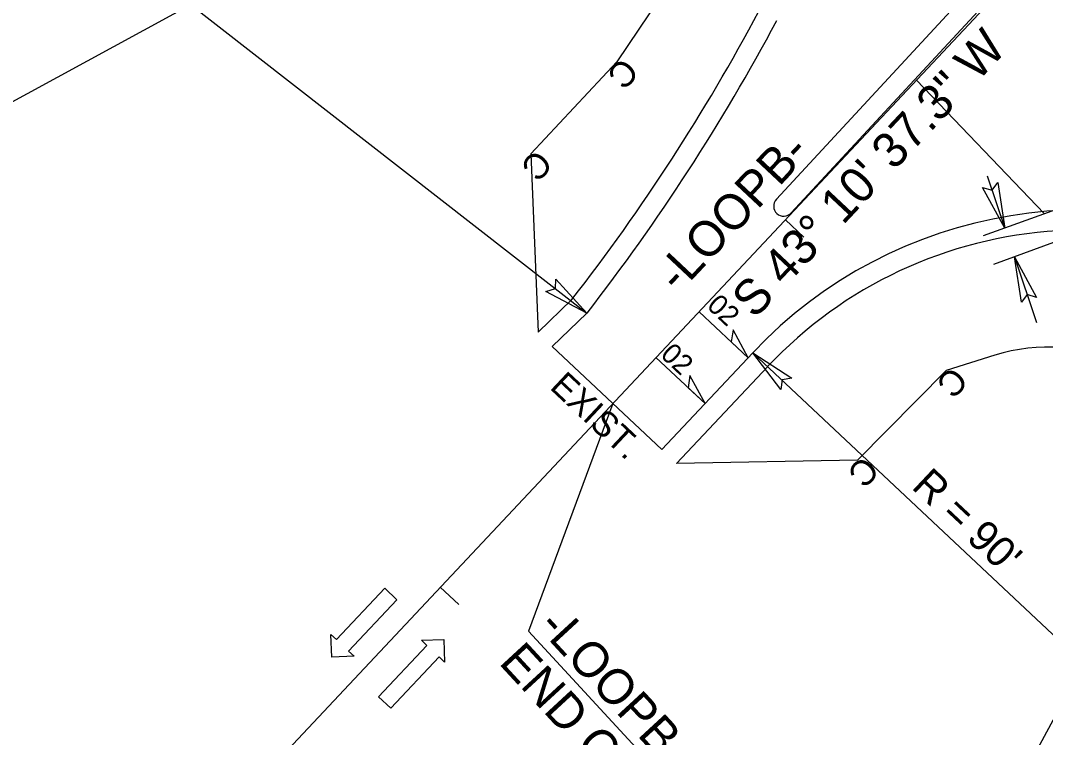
# Model space of a CAD drawing. Extents: x 1702862 to 1704514, y 793768 to 796215.
# Drawn here: x 1703113.3 to 1703316.6, y 795050.3 to 795192.6 of the extents above; entities that cross this region are included whole.
import ezdxf

# ---------------------------------------------------------------- set-up
doc = ezdxf.new("R2010")
doc.units = 0
for name, color, linetype in [('Prop Conc 5in Monolithic Surface Mount Island', 7, 'Continuous'), ('Prop Dimension', 7, 'Continuous'), ('Prop Dimension Text', 7, 'Continuous'), ('Prop DSN Text', 7, 'Continuous'), ('Prop EOT', 7, 'Continuous'), ('Prop Horizontal Alignment', 7, 'Continuous'), ('Prop Horizontal Alignment Direction Label', 7, 'Continuous'), ('Prop Horizontal Alignment Tick Small', 7, 'Continuous'), ('Prop Lane Arrow CELL', 7, 'Continuous'), ('Prop Leader Line Medium', 7, 'Continuous'), ('Prop Paved Shoulder', 7, 'Continuous'), ('Prop SS Cut Line', 7, 'Continuous'), ('Prop SS Misc', 7, 'Continuous'), ('Prop SS Transition Line', 7, 'Continuous'), ('Prop Superelevation  Arrow CELL', 7, 'Continuous'), ('Prop Superelevation Label', 7, 'Continuous'), ('Prop Terminator CELL', 7, 'Continuous')]:
    doc.layers.add(name, color=color, linetype=linetype)

msp = doc.modelspace()

# ---------------------------------------------------------------- linework, layer by layer
at = {"layer": 'Prop Conc 5in Monolithic Surface Mount Island'}
for p, q in [((1703304.39, 795201.63), (1703263.21, 795157.11)), ((1703304.39, 795201.63), (1703263.21, 795157.11)), ((1703266.15, 795154.39), (1703307.33, 795198.91)), ((1703266.15, 795154.39), (1703307.33, 795198.91))]:
    msp.add_line(p, q, dxfattribs=at)
for start, end in [(137.2317, 227.2317), (137.2317, 227.2317), (227.2317, 317.2317), (227.2317, 317.2317)]:
    msp.add_arc((1703264.68, 795155.75), 2, start, end, dxfattribs=at)
at = {"layer": 'Prop Dimension'}
for p, q in [((1702910.07, 795380.31), (1703225.66, 795134.54)), ((1702911.8, 795067.36), (1703262.92, 795258.97)), ((1703305.02, 795161.75), (1703308.5, 795151.4)), ((1703317.84, 795154.78), (1703304.2, 795149.85)), ((1703320.17, 795149.24), (1703306.25, 795144.2)), ((1703310.41, 795145.71), (1703314.8, 795132.63)), ((1703272.02, 794968.13), (1703366.77, 795144.26)), ((1703324.13, 795065.01), (1703258.57, 795126.66)), ((1703258.57, 795126.66), (1703258.57, 795126.66))]:
    msp.add_line(p, q, dxfattribs=at)
msp.add_arc((1703324.13, 795065.01), 90, 136.7565, 136.7565, dxfattribs=at)
at = {"layer": 'Prop EOT'}
for p, q in [((1703291, 795180.75), (1703316.33, 795154.29)), ((1703218.73, 795127.89), (1703225.66, 795134.54)), ((1703218.73, 795127.89), (1703240.51, 795107.45)), ((1703240.51, 795107.45), (1703258.57, 795126.66))]:
    msp.add_line(p, q, dxfattribs=at)
for centre, radius, start, end in [((1702910.07, 795380.31), 400, 322.0902, 332.0106), ((1703324.13, 795065.01), 90, 61.7203, 136.7565)]:
    msp.add_arc(centre, radius, start, end, dxfattribs=at)
at = {"layer": 'Prop Horizontal Alignment'}
msp.add_line((1703333.42, 795225.96), (1703157.53, 795038.5), dxfattribs=at)
at = {"layer": 'Prop Horizontal Alignment Tick Small'}
for p, q in [((1703265, 795153.04), (1703268.65, 795149.61)), ((1703196.57, 795080.11), (1703200.22, 795076.69))]:
    msp.add_line(p, q, dxfattribs=at)
at = {"layer": 'Prop Lane Arrow CELL'}
for p, q in [((1703175.98, 795069.73), (1703185.58, 795079.92)), ((1703185.58, 795079.92), (1703187.98, 795077.66)), ((1703187.98, 795077.66), (1703178.38, 795067.47)), ((1703175.06, 795066.27), (1703174.89, 795070.76)), ((1703174.89, 795070.76), (1703175.98, 795069.73)), ((1703184.33, 795058.38), (1703193.93, 795068.57)), ((1703192.84, 795069.6), (1703197.25, 795069.77)), ((1703193.93, 795068.57), (1703192.84, 795069.6)), ((1703197.25, 795069.77), (1703197.42, 795065.28)), ((1703179.47, 795066.44), (1703175.06, 795066.27)), ((1703178.38, 795067.47), (1703179.47, 795066.44)), ((1703196.33, 795066.31), (1703186.73, 795056.12)), ((1703197.42, 795065.28), (1703196.33, 795066.31)), ((1703186.73, 795056.12), (1703184.33, 795058.38))]:
    msp.add_line(p, q, dxfattribs=at)
at = {"layer": 'Prop Leader Line Medium'}
for p, q in [((1703230.79, 795116.57), (1703214.05, 795071.43)), ((1703214.05, 795071.43), (1703283.79, 794995.89))]:
    msp.add_line(p, q, dxfattribs=at)
at = {"layer": 'Prop Paved Shoulder'}
for p, q in [((1703215.96, 795130.77), (1703222.68, 795137.23)), ((1703243.42, 795104.71), (1703261.49, 795123.92))]:
    msp.add_line(p, q, dxfattribs=at)
for centre, radius, start, end in [((1702910.07, 795380.31), 396, 322.1318, 332.0106), ((1703324.13, 795065.01), 86, 93.4265, 136.7565)]:
    msp.add_arc(centre, radius, start, end, dxfattribs=at)
at = {"layer": 'Prop SS Cut Line'}
for p, q in [((1703245.72, 795205.41), (1703231.59, 795184.39)), ((1703231.59, 795184.39), (1703214.5, 795166.14)), ((1703306.56, 795126.16), (1703296.9, 795123.11)), ((1703296.9, 795123.11), (1703279.28, 795105.35))]:
    msp.add_line(p, q, dxfattribs=at)
at = {"layer": 'Prop SS Transition Line'}
for p, q in [((1703214.5, 795166.14), (1703215.96, 795130.77)), ((1703279.28, 795105.35), (1703243.42, 795104.71))]:
    msp.add_line(p, q, dxfattribs=at)
msp.add_arc((1703317.11, 795092.79), 35, 63.9216, 107.5505, dxfattribs=at)
at = {"layer": 'Prop Superelevation  Arrow CELL'}
for p, q in [((1703247.89, 795134.8), (1703257.63, 795125.67)), ((1703239.34, 795125.69), (1703249.07, 795116.56))]:
    msp.add_line(p, q, dxfattribs=at)
for points in [[(1703257.63, 795125.67), (1703254.63, 795131.23), (1703254.26, 795128.83)], [(1703249.07, 795116.56), (1703246.06, 795122.12), (1703245.7, 795119.72)]]:
    msp.add_lwpolyline(points, close=True, dxfattribs=at)
at = {"layer": 'Prop Terminator CELL'}
for points in [[(1703307.1, 795160.42), (1703308.5, 795151.4), (1703304.1, 795159.47), (1703305.98, 795158.89)], [(1703311.8, 795136.68), (1703310.41, 795145.71), (1703314.8, 795137.64), (1703312.92, 795138.22)], [(1703219.5, 795141.28), (1703225.66, 795134.54), (1703217.53, 795138.82), (1703219.42, 795139.38)], [(1703264.07, 795119.37), (1703258.57, 795126.66), (1703266.26, 795121.63), (1703264.33, 795121.25)]]:
    msp.add_lwpolyline(points, close=True, dxfattribs=at)

# ---------------------------------------------------------------- texts
at = {"layer": 'Prop Dimension Text'}
for s, height, rotation, p in [('EXIST.', 5, 316.823, (1703218.09, 795119.64)), ("R = 90'", 6, 316.7565, (1703289.82, 795099.86))]:
    msp.add_text(s, height=height, rotation=rotation, dxfattribs=at).set_placement(p)
at = {"layer": 'Prop DSN Text'}
for s, p in [('-LOOPB- STA 11+50', (1703215.71, 795072.18)), ('END CONST.', (1703208, 795065.06))]:
    msp.add_text(s, height=7, rotation=312.7091, dxfattribs=at).set_placement(p)
at = {"layer": 'Prop Horizontal Alignment Direction Label'}
for s, p in [('S 43%%d 10\' 37.3" W', (1703258.9, 795133.2)), ('-LOOPB-', (1703243.8, 795138.24))]:
    msp.add_text(s, height=7, rotation=46.823, dxfattribs=at).set_placement(p)
at = {"layer": 'Prop SS Misc'}
for p in [(1703232.64, 795185.51), (1703215.55, 795167.26), (1703297.95, 795124.23), (1703280.34, 795106.47)]:
    msp.add_text('C', height=5, rotation=226.823, dxfattribs=at).set_placement(p)
at = {"layer": 'Prop Superelevation Label'}
for p in [(1703249.22, 795135.73), (1703240.03, 795126.03)]:
    msp.add_text('02', height=4, rotation=316.823, dxfattribs=at).set_placement(p)

doc.saveas('drawing.dxf')
